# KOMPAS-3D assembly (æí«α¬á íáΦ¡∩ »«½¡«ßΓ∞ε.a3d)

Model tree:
1. Эскиз:1
2. Операция выдавливания:1
     Расстояние 1 = 0.5; Расстояние 2 = 3

Referenced files in D:\МОДЕЛЬ ТАНКА Т90\ДЕТАЛИ\БАШНЯ\башня сварная\: Сборка башня .a3d, тяга шторы.m3d, тяга шторы прав.m3d, Сборка люк наводчика.a3d, коробка.m3d, Сборка люк командира.a3d, коробка патрон.m3d, перескоп.m3d
Referenced files in D:\МОДЕЛЬ ТАНКА Т90\ДЕТАЛИ\БАШНЯ\башня сварная\НАВЕСКА\: Сборка штора.a3d, Сборка контакт5 левый.a3d, Сборка контакт5 правый.a3d, контакт узкий.m3d, контакт горизонт.m3d
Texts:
  Сборка башня полностью
  stalker61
